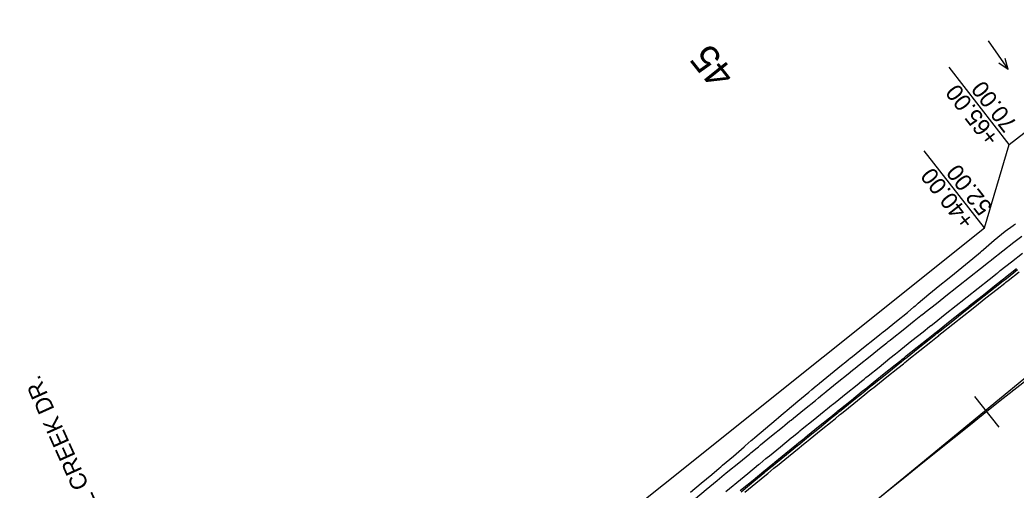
# Model space of a CAD drawing. Extents: x 1147550 to 1149124, y 2017436 to 2018779.
# Drawn here: x 1147550.1 to 1147906, y 2017707.7 to 2017875.6 of the extents above; entities that cross this region are included whole.
import ezdxf

# ---------------------------------------------------------------- set-up
doc = ezdxf.new("R2010")
doc.units = 0
for name, color, linetype in [('S_EDGE_CONCRETE', 7, 'Continuous'), ('S_ELECTRIC_UTILITIES', 7, 'Continuous'), ('S_MAILBOX', 7, 'Continuous'), ('S_RDW_PT_SYM', 7, 'Continuous'), ('S_SECONDARY_CTL', 7, 'Continuous'), ('S_STORM_SEWER', 7, 'Continuous'), ('S_TANK', 7, 'Continuous'), ('S_TELEPHONE_UTILITIES', 7, 'Continuous')]:
    doc.layers.add(name, color=color, linetype=linetype)

msp = doc.modelspace()

# ---------------------------------------------------------------- linework, layer by layer
at = {"layer": 'S_EDGE_CONCRETE'}
msp.add_line((1147825.51, 2017679.08), (1148011.14, 2017831.73), dxfattribs=at)
msp.add_lwpolyline([(1147891.1, 2017741.16), (1147899.82, 2017730.21)], dxfattribs=at)
msp.add_arc((1151464.82, 2013253.76), 5729.58, 124.62946, 129.43332, dxfattribs=at)
at = {"layer": 'S_ELECTRIC_UTILITIES'}
for points in [[(1147903.55, 2017831.14), (1147882.05, 2017858.76)], [(1147894.72, 2017801.4), (1147873.11, 2017828.93)]]:
    msp.add_lwpolyline(points, dxfattribs=at)
at = {"layer": 'S_MAILBOX'}
msp.add_lwpolyline([(1147550.1, 2017525.89), (1147894.72, 2017801.4), (1147903.55, 2017831.14), (1148035.64, 2017933.4), (1148261.5, 2018084.85), (1148285.74, 2018084.65), (1148479.1, 2018223.18), (1148835.76, 2018573.62)], dxfattribs=at)
at = {"layer": 'S_SECONDARY_CTL'}
msp.add_lwpolyline([(1147789.6, 2017706.98), (1147793.45, 2017710.16), (1147797.31, 2017713.34), (1147797.32, 2017713.35), (1147799.87, 2017715.51), (1147800.45, 2017716), (1147801.15, 2017716.61), (1147804.98, 2017719.89), (1147808.78, 2017723.2), (1147809.16, 2017723.54), (1147811.37, 2017725.43), (1147811.81, 2017725.81), (1147812.6, 2017726.48), (1147816.43, 2017729.76), (1147820.3, 2017732.99), (1147821.08, 2017733.64), (1147822.93, 2017735.2), (1147823.33, 2017735.53), (1147824.16, 2017736.23), (1147828.02, 2017739.47), (1147831.89, 2017742.69), (1147833.06, 2017743.67), (1147834.54, 2017744.91), (1147834.89, 2017745.2), (1147835.76, 2017745.93), (1147839.63, 2017749.16), (1147843.55, 2017752.33), (1147845.12, 2017753.59), (1147846.08, 2017754.35), (1147846.73, 2017754.87), (1147847.49, 2017755.47), (1147851.43, 2017758.61), (1147855.37, 2017761.75), (1147857.34, 2017763.32), (1147857.91, 2017763.77), (1147858.53, 2017764.26), (1147859.32, 2017764.89), (1147863.26, 2017768.02), (1147867.21, 2017771.15), (1147869.5, 2017773.12), (1147869.94, 2017773.5), (1147869.99, 2017773.56), (1147871.02, 2017774.46), (1147874.85, 2017777.74), (1147878.78, 2017780.9), (1147881.52, 2017783.11), (1147881.59, 2017783.17), (1147881.61, 2017783.18), (1147882.7, 2017784.06), (1147886.63, 2017787.22), (1147890.53, 2017790.41), (1147893.22, 2017792.72), (1147893.34, 2017792.83), (1147893.58, 2017793.03), (1147894.36, 2017793.7), (1147898.19, 2017796.98), (1147902.09, 2017800.18), (1147904.98, 2017802.26), (1147905.06, 2017802.32), (1147905.76, 2017802.82)], dxfattribs=at)
at = {"layer": 'S_TANK'}
for p, q in [((1147895.99, 2017868.21), (1147903.16, 2017857.89)), ((1147903.16, 2017857.89), (1147899.82, 2017860.25)), ((1147903.16, 2017857.89), (1147902.12, 2017861.85))]:
    msp.add_line(p, q, dxfattribs=at)
at = {"layer": 'S_TELEPHONE_UTILITIES'}
for points in [[(1147791.41, 2017704.77), (1147795.28, 2017707.94), (1147799.14, 2017711.12), (1147799.15, 2017711.13), (1147801.73, 2017713.25), (1147802.31, 2017713.73), (1147803.03, 2017714.32), (1147806.92, 2017717.51), (1147810.82, 2017720.7), (1147811.22, 2017721.03), (1147813.47, 2017722.87), (1147813.92, 2017723.23), (1147814.72, 2017723.89), (1147818.62, 2017727.07), (1147822.53, 2017730.25), (1147823.31, 2017730.89), (1147825.19, 2017732.42), (1147825.59, 2017732.75), (1147826.43, 2017733.43), (1147830.34, 2017736.6), (1147834.26, 2017739.77), (1147835.44, 2017740.73), (1147836.94, 2017741.94), (1147837.3, 2017742.23), (1147838.17, 2017742.94), (1147842.09, 2017746.1), (1147846.02, 2017749.26), (1147847.59, 2017750.53), (1147848.54, 2017751.29), (1147849.19, 2017751.81), (1147849.94, 2017752.42), (1147853.87, 2017755.57), (1147857.8, 2017758.72), (1147859.76, 2017760.29), (1147860.33, 2017760.75), (1147860.95, 2017761.24), (1147861.73, 2017761.87), (1147865.66, 2017765.01), (1147869.6, 2017768.15), (1147871.96, 2017770.03), (1147872.41, 2017770.39), (1147872.48, 2017770.43), (1147873.54, 2017771.28), (1147877.49, 2017774.42), (1147881.43, 2017777.55), (1147884.19, 2017779.73), (1147884.27, 2017779.79), (1147884.28, 2017779.8), (1147885.38, 2017780.67), (1147889.33, 2017783.79), (1147893.29, 2017786.91), (1147896.07, 2017789.1), (1147896.2, 2017789.2), (1147896.44, 2017789.4), (1147897.25, 2017790.03), (1147901.21, 2017793.14), (1147905.17, 2017796.25), (1147907.97, 2017798.44)], [(1147802.33, 2017707.27), (1147804.9, 2017709.39), (1147805.49, 2017709.87), (1147806.2, 2017710.45), (1147810.09, 2017713.64), (1147813.99, 2017716.83), (1147814.38, 2017717.16), (1147816.63, 2017719), (1147817.08, 2017719.36), (1147817.88, 2017720.02), (1147821.78, 2017723.2), (1147825.68, 2017726.37), (1147826.47, 2017727.02), (1147828.34, 2017728.54), (1147828.75, 2017728.87), (1147829.59, 2017729.55), (1147833.49, 2017732.72), (1147837.4, 2017735.89), (1147838.58, 2017736.84), (1147840.08, 2017738.05), (1147840.44, 2017738.34), (1147841.32, 2017739.05), (1147845.23, 2017742.21), (1147849.15, 2017745.37), (1147850.72, 2017746.63), (1147851.67, 2017747.39), (1147852.32, 2017747.92), (1147853.07, 2017748.52), (1147857, 2017751.67), (1147860.92, 2017754.82), (1147862.88, 2017756.39), (1147863.45, 2017756.84), (1147864.07, 2017757.34), (1147864.85, 2017757.96), (1147868.78, 2017761.1), (1147872.72, 2017764.24), (1147875.08, 2017766.11), (1147875.53, 2017766.47), (1147875.59, 2017766.52), (1147876.66, 2017767.37), (1147880.6, 2017770.5), (1147884.54, 2017773.63), (1147887.29, 2017775.81), (1147887.37, 2017775.87), (1147887.39, 2017775.88), (1147888.48, 2017776.75), (1147892.43, 2017779.87), (1147896.38, 2017782.98), (1147899.16, 2017785.17), (1147899.29, 2017785.27), (1147899.54, 2017785.47), (1147900.34, 2017786.1), (1147904.29, 2017789.21), (1147908.25, 2017792.31)], [(1147807.39, 2017707.55), (1147808.1, 2017708.13), (1147811.99, 2017711.32), (1147815.88, 2017714.51), (1147816.28, 2017714.84), (1147818.53, 2017716.67), (1147818.98, 2017717.04), (1147819.78, 2017717.69), (1147823.68, 2017720.87), (1147827.58, 2017724.05), (1147828.36, 2017724.69), (1147830.23, 2017726.21), (1147830.64, 2017726.54), (1147831.48, 2017727.22), (1147835.38, 2017730.39), (1147839.29, 2017733.55), (1147840.47, 2017734.51), (1147841.97, 2017735.72), (1147842.32, 2017736.01), (1147843.2, 2017736.72), (1147847.12, 2017739.88), (1147851.03, 2017743.03), (1147852.6, 2017744.29), (1147853.55, 2017745.06), (1147854.2, 2017745.58), (1147854.95, 2017746.18), (1147858.87, 2017749.33), (1147862.8, 2017752.48), (1147864.76, 2017754.05), (1147865.33, 2017754.5), (1147865.94, 2017754.99), (1147866.72, 2017755.62), (1147870.65, 2017758.76), (1147874.59, 2017761.89), (1147876.94, 2017763.77), (1147877.39, 2017764.13), (1147877.45, 2017764.17), (1147878.52, 2017765.02), (1147882.46, 2017768.15), (1147886.4, 2017771.27), (1147889.15, 2017773.45), (1147889.23, 2017773.52), (1147889.25, 2017773.53), (1147890.34, 2017774.4), (1147894.29, 2017777.51), (1147898.24, 2017780.63), (1147901.01, 2017782.81), (1147901.14, 2017782.91), (1147901.39, 2017783.11), (1147902.19, 2017783.74), (1147906.15, 2017786.85)], [(1147807.71, 2017707.16), (1147808.42, 2017707.75), (1147812.31, 2017710.94), (1147816.2, 2017714.12), (1147816.6, 2017714.45), (1147818.85, 2017716.28), (1147819.29, 2017716.65), (1147820.1, 2017717.31), (1147823.99, 2017720.48), (1147827.89, 2017723.66), (1147828.68, 2017724.3), (1147830.55, 2017725.82), (1147830.95, 2017726.15), (1147831.79, 2017726.83), (1147835.7, 2017730), (1147839.61, 2017733.17), (1147840.78, 2017734.12), (1147842.28, 2017735.33), (1147842.64, 2017735.62), (1147843.52, 2017736.33), (1147847.43, 2017739.49), (1147851.35, 2017742.64), (1147852.91, 2017743.9), (1147853.86, 2017744.67), (1147854.51, 2017745.19), (1147855.26, 2017745.79), (1147859.19, 2017748.94), (1147863.11, 2017752.09), (1147865.07, 2017753.66), (1147865.64, 2017754.11), (1147866.26, 2017754.6), (1147867.04, 2017755.23), (1147870.97, 2017758.37), (1147874.9, 2017761.5), (1147877.25, 2017763.38), (1147877.71, 2017763.73), (1147877.77, 2017763.78), (1147878.83, 2017764.63), (1147882.77, 2017767.76), (1147886.71, 2017770.88), (1147889.46, 2017773.06), (1147889.54, 2017773.12), (1147889.56, 2017773.13), (1147890.66, 2017774), (1147894.6, 2017777.12), (1147898.55, 2017780.23), (1147901.32, 2017782.42), (1147901.45, 2017782.52), (1147901.7, 2017782.72), (1147902.5, 2017783.35), (1147906.46, 2017786.45)], [(1147809.06, 2017706.98), (1147812.94, 2017710.16), (1147816.83, 2017713.35), (1147817.23, 2017713.68), (1147819.48, 2017715.51), (1147819.93, 2017715.88), (1147820.73, 2017716.53), (1147824.62, 2017719.71), (1147828.52, 2017722.88), (1147829.31, 2017723.52), (1147831.18, 2017725.04), (1147831.59, 2017725.37), (1147832.42, 2017726.06), (1147836.33, 2017729.22), (1147840.23, 2017732.39), (1147841.41, 2017733.34), (1147842.91, 2017734.55), (1147843.27, 2017734.84), (1147844.14, 2017735.55), (1147848.06, 2017738.71), (1147851.97, 2017741.86), (1147853.54, 2017743.12), (1147854.49, 2017743.89), (1147855.14, 2017744.41), (1147855.89, 2017745.01), (1147859.81, 2017748.16), (1147863.73, 2017751.31), (1147865.7, 2017752.87), (1147866.26, 2017753.33), (1147866.88, 2017753.82), (1147867.66, 2017754.45), (1147871.59, 2017757.58), (1147875.52, 2017760.72), (1147877.88, 2017762.59), (1147878.33, 2017762.95), (1147878.39, 2017763), (1147879.46, 2017763.85), (1147883.39, 2017766.98), (1147887.33, 2017770.1), (1147890.08, 2017772.28), (1147890.16, 2017772.34), (1147890.18, 2017772.35), (1147891.28, 2017773.22), (1147895.22, 2017776.34), (1147899.17, 2017779.45), (1147901.94, 2017781.63), (1147902.07, 2017781.73), (1147902.32, 2017781.93), (1147903.12, 2017782.56), (1147907.07, 2017785.67)]]:
    msp.add_lwpolyline(points, dxfattribs=at)

# ---------------------------------------------------------------- texts
at = {"layer": 'S_ELECTRIC_UTILITIES'}
for s, rotation, p in [('+65.00', 127.8835, (1147900.3, 2017833.68)), ('70.00', 127.8835, (1147906.62, 2017838.59)), ('52.00', 128.1335, (1147897.76, 2017808.87)), ('+40.00', 128.1335, (1147891.47, 2017803.93))]:
    msp.add_text(s, height=6, rotation=rotation, dxfattribs=at).set_placement(p)
at = {"layer": 'S_RDW_PT_SYM'}
msp.add_text('45', height=10, rotation=128.5335, dxfattribs=at).set_placement((1147805.92, 2017856.14))
at = {"layer": 'S_STORM_SEWER'}
msp.add_text('SHOAL CREEK DR.', height=6, rotation=114.2558, dxfattribs=at).set_placement((1147586.95, 2017682.56))

doc.saveas('drawing.dxf')
